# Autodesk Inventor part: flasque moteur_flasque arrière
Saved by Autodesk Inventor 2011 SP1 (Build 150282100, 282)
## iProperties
Created: 2010-12
Part Number: flasque moteur_flasque arrière
Document SubType Name: Modeling
Designer: eric
Density: 1 g/cm^3
Author: eric
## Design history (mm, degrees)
feature "Base1"
node "Solide1"
node "Corps solides"
node "Corps surfaciques"
